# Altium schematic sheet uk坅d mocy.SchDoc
size A4; SheetNumber: 2; SheetTotal: 3
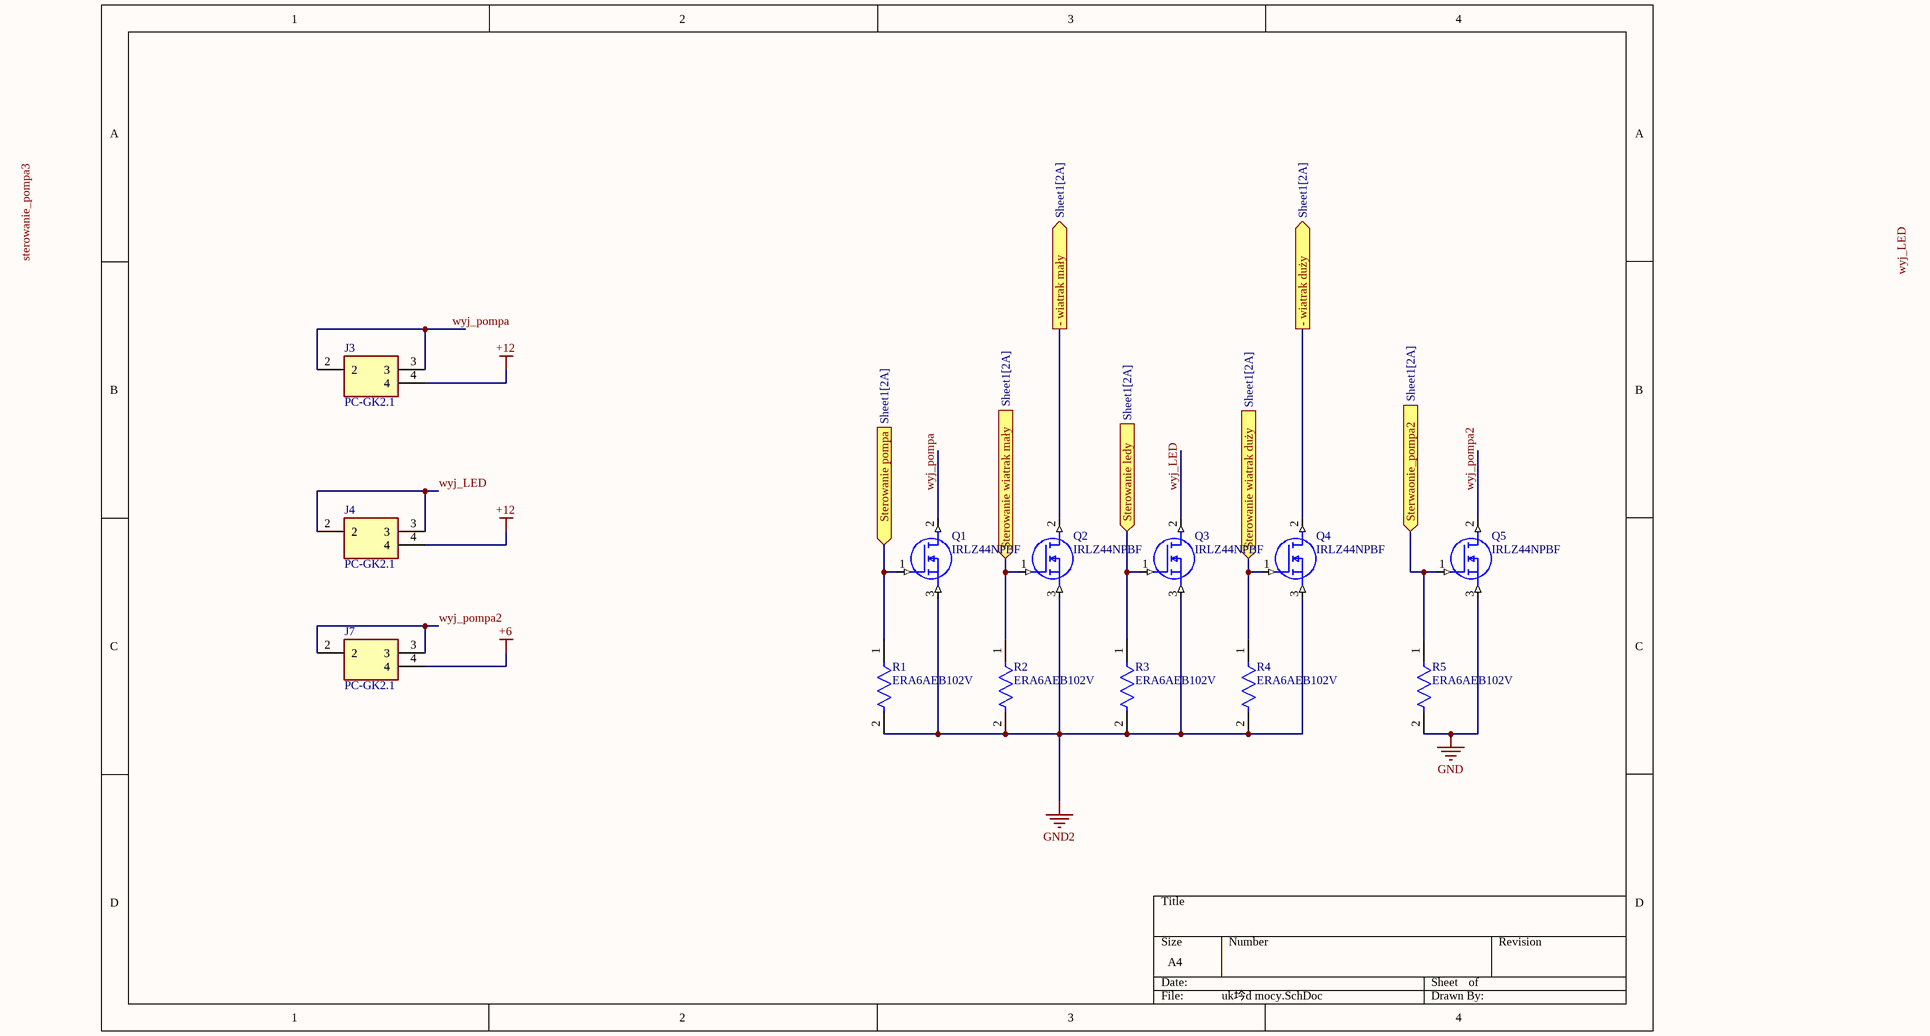
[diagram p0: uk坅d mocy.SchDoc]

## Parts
J3  PC-GK2.1  [PCGK21]
J4  PC-GK2.1  [PCGK21]
J7  PC-GK2.1  [PCGK21]
Q1  IRLZ44NPBF  [TO254P469X1042X1967-3P]
Q2  IRLZ44NPBF  [TO254P469X1042X1967-3P]
Q3  IRLZ44NPBF  [TO254P469X1042X1967-3P]
Q4  IRLZ44NPBF  [TO254P469X1042X1967-3P]
Q5  IRLZ44NPBF  [TO254P469X1042X1967-3P]
R1  ERA6AEB102V  [FP-ERA6A-IPC_C]
R2  ERA6AEB102V  [FP-ERA6A-IPC_C]
R3  ERA6AEB102V  [FP-ERA6A-IPC_C]
R4  ERA6AEB102V  [FP-ERA6A-IPC_C]
R5  ERA6AEB102V  [FP-ERA6A-IPC_C]

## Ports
- wiatrak duży (out, see Sheet1[2A]), - wiatrak mały (out, see Sheet1[2A]), Sterowanie ledy (in, see Sheet1[2A]), Sterowanie pompa (in, see Sheet1[2A]), Sterowanie wiatrak duży (in, see Sheet1[2A]), Sterowanie wiatrak mały (in, see Sheet1[2A]), Sterwaonie_pompa2 (in, see Sheet1[2A])

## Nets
+6: J7.4
+12: J3.4 J4.4
GND: Q5.3(S) R5.2
GND2: Q1.3(S) Q2.3(S) Q3.3(S) Q4.3(S) R1.2 R2.2 R3.2 R4.2
- wiatrak duży: Q4.2(D) ; port - wiatrak duży
- wiatrak mały: Q2.2(D) ; port - wiatrak mały
Sterowanie ledy: Q3.1(G) R3.1 ; port Sterowanie ledy
Sterowanie pompa: Q1.1(G) R1.1 ; port Sterowanie pompa
Sterowanie wiatrak duży: Q4.1(G) R4.1 ; port Sterowanie wiatrak duży
Sterowanie wiatrak mały: Q2.1(G) R2.1 ; port Sterowanie wiatrak mały
Sterwaonie_pompa2: Q5.1(G) R5.1 ; port Sterwaonie_pompa2
wyj_LED: J4.2 J4.3 Q3.2(D)
wyj_pompa: J3.2 J3.3 Q1.2(D)
wyj_pompa2: J7.2 J7.3 Q5.2(D)

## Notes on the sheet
- Labels drawn without touching a wire or pin: sterowanie_pompa3

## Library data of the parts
J3 J4 J7 = PC-GK2.1: Connector; Manufacturer_Name: Ninigi
Q1-Q5 = IRLZ44NPBF: MOSFET (N-Channel); Manufacturer_Name: Infineon
R1-R5 = CMP-2001-00581-2: RES 1K OHM 0.1% 1/8W 0805; Temperature Coefficient: 25ppm/°C; Resistance: 1kR; Working Voltage: 100V; Max Power Dissipation: 125mW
